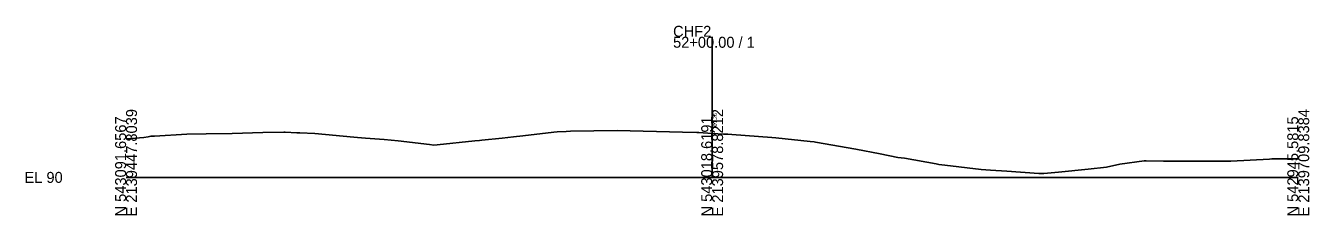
# Model space of a CAD drawing. Extents: x -12831 to 2303, y -10 to 39065.
# Drawn here: x 1974.3 to 2302.8, y 3990.3 to 4038.8 of the extents above; entities that cross this region are included whole.
import ezdxf

# ---------------------------------------------------------------- set-up
doc = ezdxf.new("R2010")
doc.units = 0
for name, color, linetype in [('RD_GPK_XS_Cell', 7, 'Continuous'), ('RD_XS_ExGround', 7, 'Continuous'), ('RD_XS_TX_Elev_EX', 7, 'Continuous')]:
    doc.layers.add(name, color=color, linetype=linetype)

msp = doc.modelspace()

# ---------------------------------------------------------------- linework, layer by layer
at = {"layer": 'RD_GPK_XS_Cell'}
for p, q in [((2150, 4000), (2150, 4035.96)), ((2000, 4000), (2150, 4000)), ((2150, 4000), (2300, 4000))]:
    msp.add_line(p, q, dxfattribs=at)
at = {"layer": 'RD_XS_ExGround'}
for p, q in [((2027.14, 4011.26), (2035.01, 4011.45)), ((2035.01, 4011.45), (2040.35, 4011.58)), ((2040.35, 4011.58), (2040.73, 4011.56)), ((2040.73, 4011.56), (2043.74, 4011.43)), ((2043.74, 4011.43), (2044.48, 4011.41)), ((2044.48, 4011.41), (2048.32, 4011.2)), ((2101.56, 4010.61), (2109.51, 4011.58)), ((2109.51, 4011.58), (2110.33, 4011.69)), ((2110.33, 4011.69), (2112.62, 4011.78)), ((2112.62, 4011.78), (2113.73, 4011.8)), ((2113.73, 4011.8), (2125.65, 4011.99)), ((2125.65, 4011.99), (2142.4, 4011.57)), ((2142.4, 4011.57), (2146.04, 4011.48)), ((2146.04, 4011.48), (2146.56, 4011.45)), ((2146.56, 4011.45), (2150, 4011.26)), ((2000, 4009.87), (2001.28, 4009.98)), ((2001.28, 4009.98), (2004.55, 4010.22)), ((2004.55, 4010.22), (2005.67, 4010.37)), ((2005.67, 4010.37), (2006.33, 4010.52)), ((2006.33, 4010.52), (2007.25, 4010.57)), ((2007.25, 4010.57), (2015.53, 4011.03)), ((2015.53, 4011.03), (2020.52, 4011.13)), ((2020.52, 4011.13), (2027.14, 4011.26)), ((2048.32, 4011.2), (2058.31, 4010.3)), ((2058.31, 4010.3), (2059.24, 4010.22)), ((2059.24, 4010.22), (2061.26, 4010.06)), ((2061.26, 4010.06), (2066.06, 4009.68)), ((2066.06, 4009.68), (2069.61, 4009.37)), ((2069.61, 4009.37), (2077.65, 4008.39)), ((2077.65, 4008.39), (2078.79, 4008.26)), ((2078.79, 4008.26), (2079.61, 4008.32)), ((2079.61, 4008.32), (2089.23, 4009.32)), ((2089.23, 4009.32), (2090.5, 4009.46)), ((2090.5, 4009.46), (2091.04, 4009.51)), ((2091.04, 4009.51), (2096.25, 4010.02)), ((2096.25, 4010.02), (2099.2, 4010.34)), ((2099.2, 4010.34), (2101.56, 4010.61)), ((2150, 4011.26), (2152.89, 4011.1)), ((2152.89, 4011.1), (2153.98, 4011.04)), ((2153.98, 4011.04), (2155.05, 4010.94)), ((2155.05, 4010.94), (2165.26, 4010.18)), ((2165.26, 4010.18), (2166.29, 4010.09)), ((2166.29, 4010.09), (2175.07, 4009.17)), ((2175.07, 4009.17), (2176.08, 4009.07)), ((2176.08, 4009.07), (2176.42, 4009.02)), ((2176.42, 4009.02), (2186.81, 4007.23)), ((2186.81, 4007.23), (2192.98, 4006.03)), ((2192.98, 4006.03), (2197.53, 4005.05)), ((2197.53, 4005.05), (2199.2, 4004.91)), ((2199.2, 4004.91), (2207.35, 4003.43)), ((2207.35, 4003.43), (2208.03, 4003.32)), ((2208.03, 4003.32), (2209.55, 4003.16)), ((2209.55, 4003.16), (2218.84, 4002.05)), ((2218.84, 4002.05), (2221.26, 4001.83)), ((2221.26, 4001.83), (2225.42, 4001.58)), ((2225.42, 4001.58), (2233.65, 4001.02)), ((2238.67, 4001.32), (2246.25, 4002.11)), ((2246.25, 4002.11), (2250.95, 4002.62)), ((2250.95, 4002.62), (2254.35, 4003.35)), ((2254.35, 4003.35), (2260.54, 4004.28)), ((2260.54, 4004.28), (2261.1, 4004.24)), ((2261.1, 4004.24), (2265.56, 4004.15)), ((2265.56, 4004.15), (2271.91, 4004.15)), ((2271.91, 4004.15), (2276.72, 4004.17)), ((2276.72, 4004.17), (2282.72, 4004.14)), ((2282.72, 4004.14), (2292.66, 4004.68)), ((2292.66, 4004.68), (2293.25, 4004.71)), ((2293.25, 4004.71), (2293.76, 4004.72)), ((2293.76, 4004.72), (2300, 4004.71)), ((2233.65, 4001.02), (2234.56, 4001.01)), ((2234.56, 4001.01), (2234.87, 4000.99)), ((2234.87, 4000.99), (2238.67, 4001.32))]:
    msp.add_line(p, q, dxfattribs=at)

# ---------------------------------------------------------------- texts
at = {"layer": 'RD_GPK_XS_Cell'}
for s, p in [('CHF2', (2140, 4035.96)), ('52+00.00 / 1', (2140, 4033.16)), ('EL 90', (1974, 3998.6))]:
    msp.add_text(s, height=2.8, dxfattribs=at).set_placement(p)
for s, p in [('N 543091.6567', (2000, 3990)), ('E 2139447.8039', (2002.8, 3990)), ('N 543018.6191', (2150, 3990)), ('E 2139578.8212', (2152.8, 3990)), ('N 542945.5815', (2300, 3990)), ('E 2139709.8384', (2302.8, 3990))]:
    msp.add_text(s, height=2.8, rotation=90, dxfattribs=at).set_placement(p)
at = {"layer": 'RD_XS_TX_Elev_EX'}
msp.add_text('101.26', height=1, rotation=90, dxfattribs=at).set_placement((2151.25, 4012.26))

doc.saveas('drawing.dxf')
